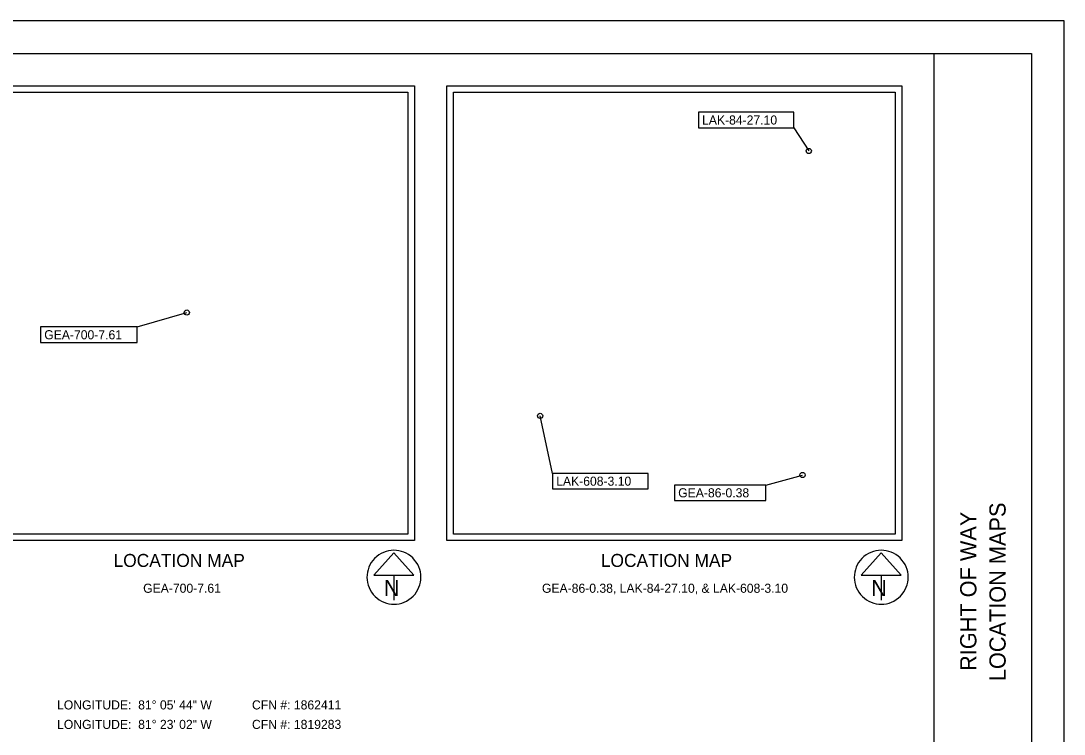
# Model space of a CAD drawing. Extents: x 0 to 34, y 0 to 22.
# Drawn here: x 17.94 to 34, y 11.02 to 22 of the extents above; entities that cross this region are included whole.
import ezdxf

# ---------------------------------------------------------------- set-up
doc = ezdxf.new("R2010")
doc.units = 0
for name, color, linetype in [('SH_Border', 7, 'Continuous'), ('SH_Cut_Line', 7, 'Continuous'), ('SH_Data', 7, 'Continuous'), ('SH_Text', 7, 'Continuous')]:
    doc.layers.add(name, color=color, linetype=linetype)

msp = doc.modelspace()

# ---------------------------------------------------------------- linework, layer by layer
at = {"layer": 'SH_Border'}
msp.add_line((32, 0.5), (32, 21.5), dxfattribs=at)
msp.add_lwpolyline([(1.5, 21.5), (33.5, 21.5), (33.5, 0.5), (1.5, 0.5)], close=True, dxfattribs=at)
at = {"layer": 'SH_Cut_Line'}
msp.add_lwpolyline([(0, 0), (34, 0), (34, 22), (0, 22)], close=True, dxfattribs=at)
at = {"layer": 'SH_Data'}
for p, q in [((23.685, 13.809), (23.377, 13.468)), ((23.992, 13.468), (23.685, 13.809)), ((31.185, 13.809), (30.877, 13.468)), ((31.492, 13.468), (31.185, 13.809)), ((23.377, 13.468), (23.992, 13.468)), ((23.685, 13.468), (23.685, 13.081)), ((23.685, 13.435), (23.685, 13.435)), ((23.685, 13.435), (23.685, 13.435)), ((30.877, 13.468), (31.492, 13.468)), ((31.185, 13.468), (31.185, 13.081)), ((31.185, 13.435), (31.185, 13.435)), ((31.185, 13.435), (31.185, 13.435))]:
    msp.add_line(p, q, dxfattribs=at)
for points in [[(17, 21), (24, 21), (24, 14), (17, 14)], [(17.1, 20.9), (23.9, 20.9), (23.9, 14.1), (17.1, 14.1)], [(24.5, 21), (31.5, 21), (31.5, 14), (24.5, 14)], [(24.6, 20.9), (31.4, 20.9), (31.4, 14.1), (24.6, 14.1)]]:
    msp.add_lwpolyline(points, close=True, dxfattribs=at)
for centre in [(23.685, 13.435), (31.185, 13.435)]:
    msp.add_arc(centre, 0.415, 129.7798, 129.7633, dxfattribs=at)
at = {"layer": 'SH_Text'}
for p, q in [((29.84, 20.354), (30.07, 19.997)), ((19.733, 17.288), (20.497, 17.51)), ((26.127, 15.034), (25.935, 15.919)), ((29.409, 14.855), (29.974, 15.009))]:
    msp.add_line(p, q, dxfattribs=at)
for points in [[(28.371, 20.594), (28.371, 20.354), (29.84, 20.354), (29.84, 20.594)], [(18.247, 17.288), (18.247, 17.048), (19.733, 17.048), (19.733, 17.288)], [(26.127, 15.034), (26.127, 14.794), (27.596, 14.794), (27.596, 15.034)], [(28.005, 14.855), (28.005, 14.615), (29.409, 14.615), (29.409, 14.855)]]:
    msp.add_lwpolyline(points, close=True, dxfattribs=at)
for centre in [(30.07, 19.997), (20.497, 17.51), (25.935, 15.919), (29.974, 15.009)]:
    msp.add_circle(centre, 0.04, dxfattribs=at)

# ---------------------------------------------------------------- texts
at = {"layer": 'SH_Data'}
for s, p in [('LOCATION MAPS', (33.1, 11.836)), ('RIGHT OF WAY', (32.65, 11.993))]:
    msp.add_text(s, height=0.25, rotation=90, dxfattribs=at).set_placement(p)
for p in [(23.529, 13.144), (31.029, 13.144)]:
    msp.add_text('N', height=0.25, dxfattribs=at).set_placement(p)
at = {"layer": 'SH_Text'}
for s, height, p in [('LAK-84-27.10', 0.14, (28.427, 20.404)), ('GEA-700-7.61', 0.14, (18.303, 17.098)), ('LAK-608-3.10', 0.14, (26.182, 14.844)), ('GEA-86-0.38', 0.14, (28.06, 14.665)), ('LOCATION MAP', 0.2, (19.369, 13.594)), ('LOCATION MAP', 0.2, (26.869, 13.594)), ('GEA-700-7.61', 0.14, (19.825, 13.196)), ('GEA-86-0.38, LAK-84-27.10, & LAK-608-3.10', 0.14, (25.963, 13.196)), ('LONGITUDE:  81° 05\' 44" W', 0.14, (18.5, 11.4)), ('CFN #: 1862411', 0.14, (21.5, 11.4)), ('LONGITUDE:  81° 23\' 02" W', 0.14, (18.5, 11.1)), ('CFN #: 1819283', 0.14, (21.5, 11.1))]:
    msp.add_text(s, height=height, dxfattribs=at).set_placement(p)

doc.saveas('drawing.dxf')
